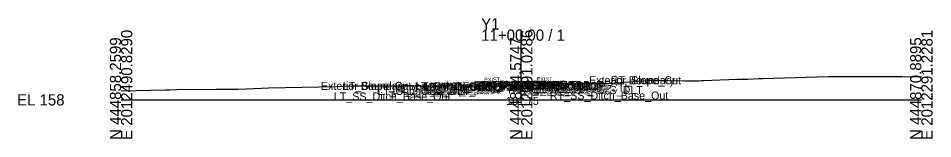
# Model space of a CAD drawing. Extents: x -26 to 3203, y -10 to 9517.
# Drawn here: x -25.7 to 202.8, y 1990.3 to 2020.4 of the extents above; entities that cross this region are included whole.
import ezdxf

# ---------------------------------------------------------------- set-up
doc = ezdxf.new("R2010")
doc.units = 0
for name, color, linetype in [('Default', 7, 'Continuous'), ('Exist Cross Section Cell', 7, 'Continuous'), ('Exist XS Center Line Elevation Label', 7, 'Continuous'), ('Exist XS Ground Line', 7, 'Continuous'), ('Prop CMT Shld Paved Course 1', 7, 'Continuous'), ('Prop XS SE Text', 7, 'Continuous'), ('Scratch_Level_0', 7, 'Continuous')]:
    doc.layers.add(name, color=color, linetype=linetype)

msp = doc.modelspace()

# ---------------------------------------------------------------- linework, layer by layer
at = {"layer": 'Exist Cross Section Cell'}
for p, q in [((100, 2000), (100, 2017.56)), ((0, 2000), (100, 2000)), ((100, 2000), (200, 2000))]:
    msp.add_line(p, q, dxfattribs=at)
at = {"layer": 'Exist XS Ground Line'}
msp.add_lwpolyline([(0, 2002.28), (11.14, 2002.52), (11.81, 2002.54), (12.21, 2002.54), (13.82, 2002.56), (23.79, 2002.66), (29.3, 2002.69), (31.28, 2002.78), (35.08, 2002.95), (36.88, 2003.01), (53.68, 2003.37), (58.11, 2003.47), (59.6, 2003.48), (63.68, 2003.48), (78.18, 2003.52), (81.28, 2003.53), (85.08, 2003.57), (85.76, 2003.44), (86.23, 2003.38), (93.85, 2003.66), (97.85, 2003.79), (100, 2003.75), (107.39, 2003.61), (109.34, 2003.59), (111.15, 2003.82), (113.57, 2003.9), (117.41, 2003.96), (122.52, 2004.17), (130.29, 2004.77), (132.54, 2004.91), (140.99, 2004.73), (144.14, 2004.77), (144.47, 2004.78), (145.02, 2004.8), (145.56, 2004.81), (153.99, 2005.15), (155.05, 2005.15), (156.63, 2005.15), (159.36, 2005.33), (160.35, 2005.33), (176.73, 2005.85), (195.26, 2005.82), (200, 2005.79)], dxfattribs=at)
at = {"layer": 'Prop CMT Shld Paved Course 1'}
msp.add_lwpolyline([(85.08, 2003.33), (85.08, 2003.33)], dxfattribs=at)

# ---------------------------------------------------------------- texts
at = {"layer": 'Default'}
msp.add_text('-', height=0.0001, dxfattribs=at).set_placement((0, 2000))
at = {"layer": 'Exist Cross Section Cell'}
for s, p in [('Y1', (90, 2017.56)), ('11+00.00 / 1', (90, 2014.76)), ('EL 158', (-26, 1998.6))]:
    msp.add_text(s, height=2.8, dxfattribs=at).set_placement(p)
for s, p in [('E 2012490.8290', (2.8, 1990)), ('E 2012391.0286', (102.8, 1990)), ('E 2012291.2281', (202.8, 1990)), ('N 444858.2599', (0, 1990)), ('N 444864.5747', (100, 1990)), ('N 444870.8895', (200, 1990))]:
    msp.add_text(s, height=2.8, rotation=90, dxfattribs=at).set_placement(p)
at = {"layer": 'Exist XS Center Line Elevation Label'}
msp.add_text('161.75', height=2, dxfattribs=at).set_placement((96.22, 1998.75))
at = {"layer": 'Prop XS SE Text'}
for rotation, p in [(1.7184, (90.74, 2004.5)), (358.8542, (103.82, 2004.7))]:
    msp.add_text('EXIST.', height=1, rotation=rotation, dxfattribs=at).set_placement(p)
at = {"layer": 'Scratch_Level_0'}
for s, p in [('Exterior Boundary', (49.94, 2002.49)), ('LT_Slope_Cut', (55.44, 2002.49)), ('LT_Sub Tie Out', (73.42, 2002.4)), ('LT_PV_OEEOP_EG', (73.62, 2002.4)), ('LT_PV1_OEOT', (75.82, 2002.33)), ('LT_PS1_OEOP', (75.88, 2002.33)), ('LT_PV1_OEEOP', (75.95, 2002.24)), ('RT_PV_IEEOP_EG', (88.14, 2002.75)), ('LT_PV_IEEOP_EG', (88.19, 2002.75)), ('RT_PV2_IEEOP', (89.91, 2002.53)), ('LT_PV2_IEEOP', (89.95, 2002.53)), ('RT_PV1_IEEOP', (90.47, 2002.65)), ('LT_PV1_IEEOP', (90.52, 2002.65)), ('PV2_PGL', (93.91, 2002.53)), ('PV1_PGL', (94.47, 2002.78)), ('RT_Sub Tie Out', (97.43, 2002.69)), ('RT_PV_OEEOP_EG', (97.63, 2002.69)), ('RT_PV2_OEEOP', (99.4, 2002.33)), ('RT_PV1_OEEOP', (99.97, 2002.45)), ('RT_PV2_OEOT', (101.27, 2002.31)), ('RT_PS2_OEOP', (101.59, 2002.3)), ('RT_PV1_OEOT', (101.84, 2002.56)), ('RT_PS1_OEOP', (101.9, 2002.56)), ('Exterior Boundary', (116.95, 2003.9)), ('RT_Slope_Cut', (122.4, 2003.9)), ('LT_SS_Ditch_Base_Out', (53.16, 1999.85)), ('LT_Sub_OSS_DLT', (64.06, 2001.25)), ('LT_Sub_Trench_Out', (67.85, 2001.38)), ('LT_GS_OS_CTL', (68.45, 2001.85)), ('LT_PS3_Shelf_Out', (69.97, 2001.73)), ('LT_PS3_OEOP', (74.72, 2001.74)), ('LT_PS2_OEOP', (75.06, 2002.08)), ('LT_Sub_OEOT', (75.16, 2001.41)), ('LT_PV2_OEOT', (75.25, 2002.08)), ('LT_PV3_OEOT', (75.25, 2001.75)), ('LT_Sub_OEEOP', (75.29, 2001.44)), ('LT_PV2_OEEOP', (75.38, 2002.11)), ('LT_PV3_OEEOP', (75.38, 2001.78)), ('RT_PV3_IEEOP', (89.91, 2002.19)), ('LT_PV3_IEEOP', (89.95, 2002.19)), ('RT_Sub_Trench_Out', (96.74, 2001.61)), ('RT_PS3_Shelf_Out', (98.18, 2001.95)), ('RT_Sub_OEEOP', (99.31, 2001.66)), ('RT_PV3_OEEOP', (99.4, 2001.99)), ('RT_Sub_OEOT', (101.18, 2001.64)), ('RT_PV3_OEOT', (101.27, 2001.97)), ('RT_PS3_OEOP', (101.93, 2001.96)), ('RT_GS_OS_CTL', (106.47, 2002.08)), ('RT_Sub_OSS_DLT', (106.92, 2001.47)), ('RT_SS_Ditch_Base_Out', (107.18, 2000.08))]:
    msp.add_text(s, height=2, dxfattribs=at).set_placement(p)

doc.saveas('drawing.dxf')
